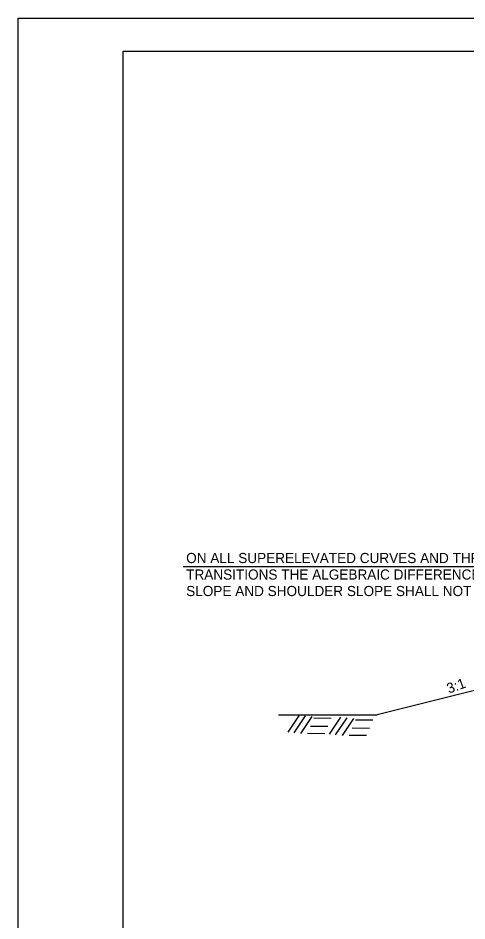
# Model space of a CAD drawing. Extents: x 1371763 to 1372860, y 385599 to 385872.
# Drawn here: x 1372493 to 1372519.5, y 385651.9 to 385705.3 of the extents above; entities that cross this region are included whole.
import ezdxf

# ---------------------------------------------------------------- set-up
doc = ezdxf.new("R2010")
doc.units = 0
for name, color, linetype in [('R_Border', 7, 'Continuous'), ('R_Draft', 7, 'Continuous'), ('R_Fin Surface', 7, 'Continuous'), ('R_No Plot', 7, 'Continuous')]:
    doc.layers.add(name, color=color, linetype=linetype)

msp = doc.modelspace()

# ---------------------------------------------------------------- linework, layer by layer
at = {"layer": 'R_Border'}
for p, q in [((1372499.208, 385703.307), (1372657.298, 385703.307)), ((1372499.208, 385600.577), (1372499.208, 385703.307))]:
    msp.add_line(p, q, dxfattribs=at)
at = {"layer": 'R_Draft'}
for p, q in [((1372502.752, 385672.85), (1372531.426, 385672.85)), ((1372523.919, 385666.526), (1372514.218, 385664.101)), ((1372508.953, 385663.07), (1372509.629, 385664.071)), ((1372509.312, 385663.028), (1372509.988, 385664.03)), ((1372509.712, 385662.986), (1372510.388, 385663.988)), ((1372510.488, 385663.913), (1372511.506, 385663.905)), ((1372511.406, 385662.961), (1372512.082, 385663.963)), ((1372511.765, 385662.92), (1372512.44, 385663.921)), ((1372512.165, 385662.878), (1372512.841, 385663.879)), ((1372512.941, 385663.804), (1372513.959, 385663.796)), ((1372510.288, 385663.429), (1372511.306, 385663.42)), ((1372512.741, 385663.32), (1372513.759, 385663.312)), ((1372510.113, 385663.003), (1372511.131, 385662.995)), ((1372512.566, 385662.895), (1372513.583, 385662.886))]:
    msp.add_line(p, q, dxfattribs=at)
at = {"layer": 'R_Fin Surface'}
msp.add_line((1372508.4, 385664.101), (1372514.218, 385664.101), dxfattribs=at)
at = {"layer": 'R_No Plot'}
msp.add_line((1372493.007, 385705.254), (1372659.674, 385705.254), dxfattribs=at)
for points in [[(1372493.004, 385705.254), (1372659.674, 385705.254), (1372659.674, 385598.585), (1372493.004, 385598.585)], [(1372616.168, 385703.307), (1372625.978, 385703.307), (1372625.978, 385698.367), (1372634.034, 385698.367), (1372645.634, 385698.367), (1372645.634, 385682.032), (1372657.238, 385682.032), (1372657.298, 385600.577), (1372499.208, 385600.577), (1372499.208, 385703.307)]]:
    msp.add_lwpolyline(points, close=True, dxfattribs=at)

# ---------------------------------------------------------------- texts
at = {"layer": 'R_Draft'}
for s, p in [('ON ALL SUPERELEVATED CURVES AND THRU SUPERELEVATION', (1372502.936, 385673.059)), ('TRANSITIONS THE ALGEBRAIC DIFFERENCE BETWEEN PAVEMENT', (1372502.936, 385672.084)), ("SLOPE AND SHOULDER SLOPE SHALL NOT EXCEED 0.08'/'", (1372502.936, 385671.109))]:
    msp.add_text(s, height=0.6, dxfattribs=at).set_placement(p)
msp.add_text('3:1', height=0.6, rotation=19.9978, dxfattribs=at).set_placement((1372518.459, 385665.343))

doc.saveas('drawing.dxf')
